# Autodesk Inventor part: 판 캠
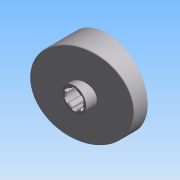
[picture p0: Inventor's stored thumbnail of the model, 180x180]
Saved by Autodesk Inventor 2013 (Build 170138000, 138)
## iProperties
Created: 2012-05
Part Number: 판 캠
Document SubType Name: 모델링
Designer: SeoGD™
Material: 강철
Mass: 681.586 g
Surface Area: 331.301 cm^2
Volume: 86.8262 cm^3
Density: 7.85 g/cm^3
변환 표준: STEP AP214IS
파일 이름: C:\Users\SeoGD\Desktop\?쒗뿕\??stp
전처리기: Build: 253, Release: 2010 SP1 - Date: Wed 07/29/2009
전송 단위: 밀리미터
불확실성: 0.01
Author: SeoGD™
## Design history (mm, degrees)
node "작업 평면4"
sketch "스케치1"
  geometry: C1 r 44.5 at (0, 0); 1 further point
  constraints: 1 centre point, 1 coincident
  dimensions: "d25" = 89 diameter of C1
extrude "돌출1" new body sketch "스케치1" distance "d1" = 40; taper "d2" = 0 deg
sketch "스케치2"
  geometry: L1 (-44.5, 15)-(44.5, 38.847); L2 (-44.5, 0)-(-44.5, 40) reference; L3 (-44.5, 40)-(44.5, 40) reference; L4 (44.5, 0)-(44.5, 40) reference; 1 further point
  constraints: 2 end point, 2 point on line
  dimensions: "d26" = 15 distance of L2.start L1.start; "d27" = 75 deg angle of L1 L2
extrude "돌출2" cut sketch "스케치2" stored distance "d5" = 40; taper "d6" = 0 deg
node "작업 평면1"
sketch "스케치3"
  geometry: C1 r 13 at (0, 0); 1 further point
  constraints: 1 centre point, 1 coincident
  dimensions: "d9" = 26 diameter of C1
extrude "돌출3" join sketch "스케치3" distance "d10" = 38; taper "d11" = 0 deg
hole "구멍1" diameter "d14" = 18; stored, may be unused: countersink angle "d18" = 90 deg, drill point angle "d20" = 118 deg; dims "d12" = 10, "d13" = 10, "d15" = 6, "d16" = 4, "d17" = 2, "d19" = 8
feature "쉘2" dims "d29" = 5
sketch "스케치6"
  geometry: C1 r 17.5 at (0, 0); C2 r 14 at (0, 0) reference; 1 further point
  constraints: 1 centre point, 1 coincident
  dimensions: "d28" = 35 diameter of C1
extrude "돌출4" join sketch "스케치6" stored distance "d30" = 38; taper "d31" = 0 deg
fillet "모깎기1" dims "d32" = 3
chamfer "모따기1" distance "d21" = 1; stored, may be unused: second distance "d22" = 2, angle "d23" = 45 deg
sketch "스케치7"
  geometry: L1 (-12.374, 12.374)-(-27.931, 27.931); A1 r 39.5 centre (0, 0) between (-27.931, 27.931) and (0, 39.5) reference; 2 further points
  constraints: 2 end point, 2 point on circle, 1 point on line, 1 vertical alignment, 2 other
  dimensions: "d33" = 45 deg dimension on point (0, 0) L1.start A1.end
feature "리브1" sketch "스케치7" dims "d34" = 5, "d35" = 1, "d36" = 0
fillet "모깎기2" dims "d37" = 3
sketch "스케치8"
  geometry: L1 (2.5, 10.712)-(2.5, 8.646); L2 (-2.5, 10.712)-(-2.5, 8.646); A1 r 11 centre (0, 0) between (2.5, 10.712) and (-2.5, 10.712); A2 r 9 centre (0, 0) between (2.5, 8.646) and (-2.5, 8.646) reference; 1 further point
  constraints: 4 end point, 4 point on circle, 2 parallel, 1 centre point, 1 coincident, 1 vertical
  dimensions: "d41" = 22 diameter of A1; "d42" = 5 distance between parallel lines of L1 L2
extrude "돌출5" cut sketch "스케치8" stored distance "d43" = 38; taper "d44" = 0 deg
fillet "모깎기3" dims "d48" = 1
node "솔리드1"
node "솔리드 본체"
node "곡면 본체"
pattern_circular "원형 패턴1" dims angle "d39" = 360 deg
pattern_circular "원형 패턴2" dims angle "d46" = 360 deg
node "솔리드2"
